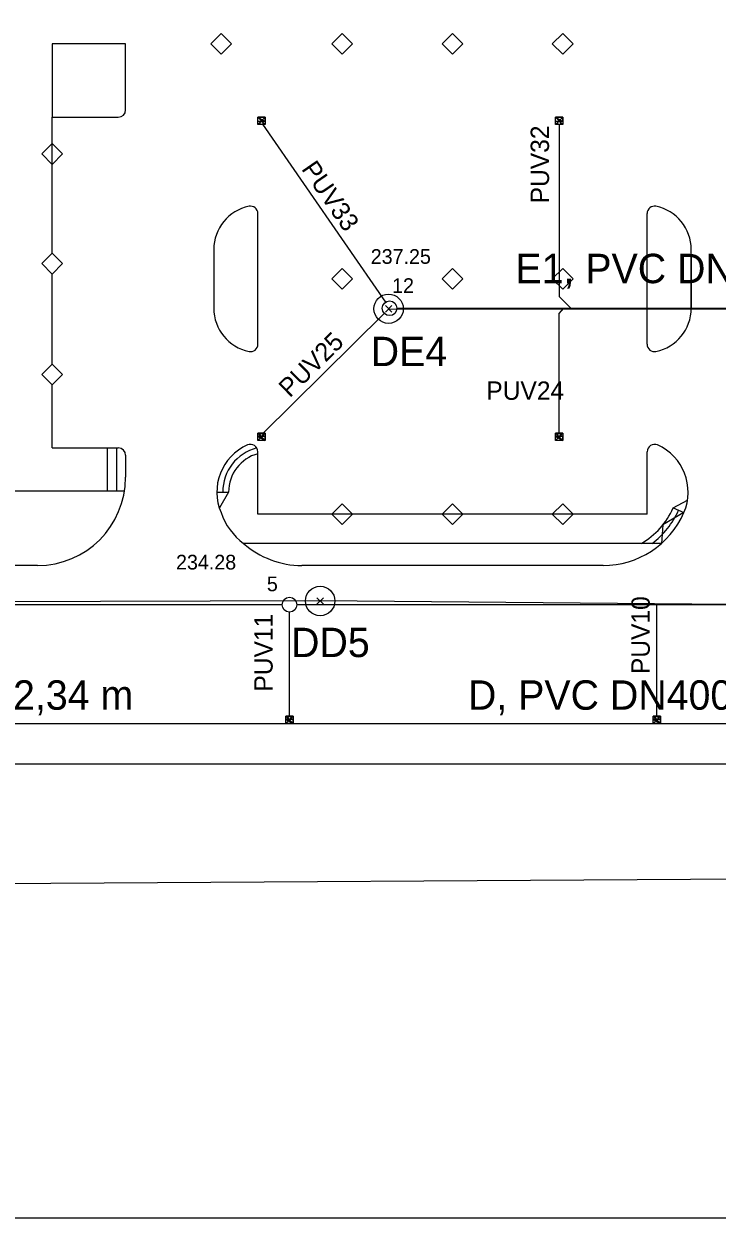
# Model space of a CAD drawing. Extents: x -264234 to -263604, y -1242346 to -1242049.
# Drawn here: x -263972 to -263924.8, y -1242345.9 to -1242264.6 of the extents above; entities that cross this region are included whole.
import ezdxf

# ---------------------------------------------------------------- set-up
doc = ezdxf.new("R2010")
doc.units = 0
for name, color, linetype in [('KFA_BODY_CISLO', 7, 'Continuous'), ('KFA_BODY_SYMBOL', 7, 'Continuous'), ('KFA_BODY_VYSKA', 7, 'Continuous'), ('KFA_DAZDOVA_KANALIZACIA_vetva_D', 7, 'Continuous'), ('KFA_DAZDOVA_KANALIZACIA_vetva_D_popis', 7, 'Continuous'), ('KFA_DAZDOVA_KANALIZACIA_vetva_E', 7, 'Continuous'), ('KFA_DAZDOVA_KANALIZACIA_vetva_E_popis', 7, 'Continuous'), ('KFA_SITUACIA_DSP', 7, 'Continuous'), ('KFA_SO_40-2-II_DK_PRIPOJKY_UV_PROJEKT', 7, 'Continuous'), ('KFA_SO_40-2-II_DK_PRIPOJKY_UV_PROJEKT_popis', 7, 'Continuous'), ('KFA_SO_40-2-II_DK_UV_PROJEKT', 7, 'Continuous'), ('RAM_NA_TLAC_1-500', 7, 'Continuous')]:
    doc.layers.add(name, color=color, linetype=linetype)

msp = doc.modelspace()

# ---------------------------------------------------------------- linework, layer by layer
at = {"layer": 'KFA_BODY_SYMBOL'}
for p, q in [((-263947.392, -1242284.234), (-263946.95, -1242283.792)), ((-263946.95, -1242284.234), (-263947.392, -1242283.792)), ((-263952.051, -1242304.117), (-263951.609, -1242303.675)), ((-263951.609, -1242304.117), (-263952.051, -1242303.675))]:
    msp.add_line(p, q, dxfattribs=at)
at = {"layer": 'KFA_DAZDOVA_KANALIZACIA_vetva_D'}
msp.add_lwpolyline([(-263821.591, -1242304.454), (-263853.822, -1242304.119), (-263903.787, -1242304.318), (-263951.83, -1242303.896), (-264004.174, -1242304.048), (-264044.816, -1242304.218), (-264095.209, -1242304.148), (-264105.621, -1242304.173)], dxfattribs=at)
msp.add_circle((-263951.83, -1242303.896), 1, dxfattribs=at)
at = {"layer": 'KFA_DAZDOVA_KANALIZACIA_vetva_E'}
msp.add_line((-263947.171, -1242284.013), (-263904.009, -1242284.08), dxfattribs=at)
msp.add_circle((-263947.171, -1242284.013), 1, dxfattribs=at)
at = {"layer": 'KFA_SITUACIA_DSP'}
for p, q in [((-263965.068, -1242265.982), (-263970.068, -1242265.982)), ((-263965.068, -1242270.482), (-263965.068, -1242265.982)), ((-263970.065, -1242280.238), (-263970.068, -1242270.982)), ((-263956.068, -1242270.982), (-263955.568, -1242270.982)), ((-263956.068, -1242271.272), (-263956.068, -1242270.982)), ((-263956.068, -1242270.982), (-263955.568, -1242271.272)), ((-263956.068, -1242270.982), (-263955.568, -1242271.272)), ((-263955.568, -1242270.982), (-263956.068, -1242270.982)), ((-263955.568, -1242271.272), (-263956.068, -1242271.272)), ((-263955.761, -1242271.455), (-263947.392, -1242283.571)), ((-263955.568, -1242270.982), (-263955.568, -1242271.272)), ((-263955.568, -1242271.272), (-263955.568, -1242270.982)), ((-263935.824, -1242270.983), (-263935.324, -1242270.983)), ((-263935.824, -1242271.273), (-263935.824, -1242270.983)), ((-263935.824, -1242270.983), (-263935.324, -1242271.273)), ((-263935.824, -1242270.983), (-263935.324, -1242271.273)), ((-263935.324, -1242270.983), (-263935.824, -1242270.983)), ((-263935.324, -1242271.273), (-263935.824, -1242271.273)), ((-263935.574, -1242271.473), (-263935.574, -1242283.187)), ((-263935.324, -1242270.983), (-263935.324, -1242271.273)), ((-263935.324, -1242271.273), (-263935.324, -1242270.983)), ((-263956.068, -1242286.432), (-263956.068, -1242277.533)), ((-263929.58, -1242286.432), (-263929.58, -1242277.533)), ((-263959.068, -1242279.982), (-263959.068, -1242283.982)), ((-263926.58, -1242283.982), (-263926.58, -1242279.982)), ((-263926.58, -1242280.482), (-263926.58, -1242283.982)), ((-263970.068, -1242287.775), (-263970.068, -1242281.649)), ((-263935.574, -1242283.187), (-263934.779, -1242283.982)), ((-263955.747, -1242292.522), (-263947.464, -1242284.334)), ((-263946.608, -1242283.982), (-263908.955, -1242283.982)), ((-263946.608, -1242283.982), (-263904.413, -1242283.982)), ((-263935.574, -1242284.343), (-263935.249, -1242283.982)), ((-263935.574, -1242292.492), (-263935.574, -1242284.343)), ((-263970.068, -1242293.482), (-263970.068, -1242289.189)), ((-263956.068, -1242292.692), (-263955.568, -1242292.692)), ((-263956.068, -1242292.982), (-263956.068, -1242292.692)), ((-263956.068, -1242292.692), (-263955.568, -1242292.982)), ((-263956.068, -1242292.692), (-263955.568, -1242292.982)), ((-263955.568, -1242292.692), (-263956.068, -1242292.692)), ((-263955.568, -1242292.982), (-263956.068, -1242292.982)), ((-263955.568, -1242292.692), (-263955.568, -1242292.982)), ((-263955.568, -1242292.982), (-263955.568, -1242292.692)), ((-263935.824, -1242292.692), (-263935.324, -1242292.692)), ((-263935.824, -1242292.982), (-263935.824, -1242292.692)), ((-263935.824, -1242292.692), (-263935.324, -1242292.982)), ((-263935.824, -1242292.692), (-263935.324, -1242292.982)), ((-263935.324, -1242292.692), (-263935.824, -1242292.692)), ((-263935.324, -1242292.982), (-263935.824, -1242292.982)), ((-263935.324, -1242292.692), (-263935.324, -1242292.982)), ((-263935.324, -1242292.982), (-263935.324, -1242292.692)), ((-263970.068, -1242293.482), (-263965.568, -1242293.482)), ((-263966.314, -1242293.482), (-263966.314, -1242296.432)), ((-263965.684, -1242293.482), (-263965.684, -1242296.432)), ((-263965.068, -1242293.982), (-263965.068, -1242295.482)), ((-263956.068, -1242297.982), (-263956.068, -1242293.737)), ((-263929.58, -1242297.982), (-263929.58, -1242293.737)), ((-263927.814, -1242297.562), (-263926.833, -1242297.035)), ((-263929.58, -1242297.982), (-263956.068, -1242297.982)), ((-263927.814, -1242297.562), (-263927.081, -1242297.882)), ((-263928.612, -1242299.982), (-263957.036, -1242299.982)), ((-263971.068, -1242301.482), (-264112.961, -1242301.482)), ((-263932.58, -1242301.482), (-263953.068, -1242301.482)), ((-263954.413, -1242304.147), (-264003.396, -1242304.147)), ((-263953.913, -1242311.742), (-263953.913, -1242304.647)), ((-263904.413, -1242304.147), (-263953.413, -1242304.147)), ((-263928.913, -1242311.742), (-263928.913, -1242304.147)), ((-263954.163, -1242311.942), (-263953.663, -1242311.942)), ((-263954.163, -1242312.232), (-263954.163, -1242311.942)), ((-263954.163, -1242311.942), (-263953.663, -1242312.232)), ((-263954.163, -1242311.942), (-263953.663, -1242312.232)), ((-263953.663, -1242311.942), (-263954.163, -1242311.942)), ((-263953.663, -1242311.942), (-263953.663, -1242312.232)), ((-263953.663, -1242312.232), (-263953.663, -1242311.942)), ((-263929.163, -1242311.942), (-263928.663, -1242311.942)), ((-263929.163, -1242312.232), (-263929.163, -1242311.942)), ((-263929.163, -1242311.942), (-263928.663, -1242312.232)), ((-263929.163, -1242311.942), (-263928.663, -1242312.232)), ((-263928.663, -1242311.942), (-263929.163, -1242311.942)), ((-263928.663, -1242311.942), (-263928.663, -1242312.232)), ((-263928.663, -1242312.232), (-263928.663, -1242311.942)), ((-263980.94, -1242312.232), (-263857.327, -1242312.232)), ((-263953.663, -1242312.232), (-263954.163, -1242312.232)), ((-263928.663, -1242312.232), (-263929.163, -1242312.232)), ((-264038.443, -1242314.982), (-263836.403, -1242314.982)), ((-263976.89, -1242323.14), (-263880.39, -1242322.51))]:
    msp.add_line(p, q, dxfattribs=at)
for points in [[(-263958.568, -1242265.275), (-263957.861, -1242265.982), (-263958.568, -1242266.689), (-263959.275, -1242265.982)], [(-263950.324, -1242265.275), (-263949.617, -1242265.982), (-263950.324, -1242266.689), (-263951.031, -1242265.982)], [(-263942.824, -1242265.275), (-263942.117, -1242265.982), (-263942.824, -1242266.689), (-263943.531, -1242265.982)], [(-263935.324, -1242265.275), (-263934.617, -1242265.982), (-263935.324, -1242266.689), (-263936.031, -1242265.982)], [(-263970.068, -1242272.775), (-263969.361, -1242273.482), (-263970.068, -1242274.189), (-263970.775, -1242273.482)], [(-263970.068, -1242280.235), (-263969.361, -1242280.942), (-263970.068, -1242281.649), (-263970.775, -1242280.942)], [(-263950.324, -1242281.275), (-263949.617, -1242281.982), (-263950.324, -1242282.689), (-263951.031, -1242281.982)], [(-263942.824, -1242281.275), (-263942.117, -1242281.982), (-263942.824, -1242282.689), (-263943.531, -1242281.982)], [(-263935.324, -1242281.275), (-263934.617, -1242281.982), (-263935.324, -1242282.689), (-263936.031, -1242281.982)], [(-263970.068, -1242287.775), (-263969.361, -1242288.482), (-263970.068, -1242289.189), (-263970.775, -1242288.482)], [(-263949.617, -1242297.982), (-263950.324, -1242297.275), (-263951.031, -1242297.982), (-263950.324, -1242298.689)], [(-263942.117, -1242297.982), (-263942.824, -1242297.275), (-263943.531, -1242297.982), (-263942.824, -1242298.689)], [(-263934.617, -1242297.982), (-263935.324, -1242297.275), (-263936.031, -1242297.982), (-263935.324, -1242298.689)]]:
    msp.add_lwpolyline(points, close=True, dxfattribs=at)
for points in [[(-263970.068, -1242265.982), (-263970.068, -1242270.982), (-263965.568, -1242270.982)], [(-263965.143, -1242296.432), (-264120.018, -1242296.432), (-264120.282, -1242296.432)], [(-263958.859, -1242296.482), (-263958.059, -1242296.482), (-263958.688, -1242297.562)], [(-263927.081, -1242297.882), (-263928.506, -1242298.713), (-263928.612, -1242299.982)]]:
    msp.add_lwpolyline(points, dxfattribs=at)
for centre, radius in [((-263955.818, -1242271.373), 0.1), ((-263935.574, -1242271.373), 0.1), ((-263947.108, -1242283.982), 0.5), ((-263955.818, -1242292.592), 0.1), ((-263935.574, -1242292.592), 0.1), ((-263953.913, -1242304.147), 0.5), ((-263953.913, -1242311.842), 0.1), ((-263928.913, -1242311.842), 0.1)]:
    msp.add_circle(centre, radius, dxfattribs=at)
for centre, radius, start, end in [((-263965.568, -1242270.482), 0.5, 270, 0), ((-263956.068, -1242279.982), 3, 101.53696, 180), ((-263956.568, -1242277.533), 0.5, 0, 101.53696), ((-263929.08, -1242277.533), 0.5, 78.46304, 180), ((-263929.58, -1242279.982), 3, 0, 78.46304), ((-263956.068, -1242283.982), 3, 180, 258.46304), ((-263929.58, -1242283.982), 3, 281.53696, 0), ((-263956.568, -1242286.432), 0.5, 258.46304, 0), ((-263929.08, -1242286.432), 0.5, 180, 281.53696), ((-263955.359, -1242296.482), 3.5, 113.75985, 203.57818), ((-263956.568, -1242293.737), 0.5, 0, 113.75985), ((-263929.08, -1242293.737), 0.5, 66.24015, 180), ((-263930.289, -1242296.482), 3.5, 336.42182, 66.24015), ((-263965.568, -1242293.982), 0.5, 0, 90), ((-263955.359, -1242296.482), 3.1, 104.54571, 180), ((-263955.359, -1242296.482), 2.7, 105.21758, 180), ((-263971.068, -1242295.482), 6, 270, 0), ((-263954.444, -1242296.485), 4.353, 198.7173, 233.45125), ((-263932.58, -1242295.482), 6, 270, 336.42182), ((-263932.58, -1242295.482), 5.2, 300.07335, 336.42182), ((-263932.58, -1242295.482), 5.6, 306.52749, 336.42182), ((-263953.068, -1242295.482), 6, 228.59038, 270)]:
    msp.add_arc(centre, radius, start, end, dxfattribs=at)
at = {"layer": 'KFA_SO_40-2-II_DK_PRIPOJKY_UV_PROJEKT'}
for points in [[(-263955.761, -1242271.455), (-263947.392, -1242283.571)], [(-263935.574, -1242271.473), (-263935.574, -1242283.187), (-263934.779, -1242283.982)], [(-263955.747, -1242292.522), (-263947.464, -1242284.334)], [(-263935.574, -1242292.492), (-263935.574, -1242284.343), (-263935.249, -1242283.982)], [(-263953.913, -1242311.742), (-263953.913, -1242304.647)], [(-263928.913, -1242311.742), (-263928.913, -1242304.147)]]:
    msp.add_lwpolyline(points, dxfattribs=at)
at = {"layer": 'KFA_SO_40-2-II_DK_UV_PROJEKT'}
for points in [[(-263956.068, -1242271.482), (-263956.068, -1242270.982), (-263955.568, -1242270.982), (-263955.568, -1242271.482), (-263956.068, -1242271.482), (-263955.568, -1242270.982), (-263956.068, -1242270.982), (-263955.568, -1242271.482)], [(-263935.824, -1242271.483), (-263935.824, -1242270.983), (-263935.324, -1242270.983), (-263935.324, -1242271.483), (-263935.824, -1242271.483), (-263935.324, -1242270.983), (-263935.824, -1242270.983), (-263935.324, -1242271.483)], [(-263956.068, -1242292.982), (-263956.068, -1242292.482), (-263955.568, -1242292.482), (-263955.568, -1242292.982), (-263956.068, -1242292.982), (-263955.568, -1242292.482), (-263956.068, -1242292.482), (-263955.568, -1242292.982)], [(-263935.824, -1242292.982), (-263935.824, -1242292.482), (-263935.324, -1242292.482), (-263935.324, -1242292.982), (-263935.824, -1242292.982), (-263935.324, -1242292.482), (-263935.824, -1242292.482), (-263935.324, -1242292.982)], [(-263954.163, -1242312.232), (-263954.163, -1242311.732), (-263953.663, -1242311.732), (-263953.663, -1242312.232), (-263954.163, -1242312.232), (-263953.663, -1242311.732), (-263954.163, -1242311.732), (-263953.663, -1242312.232)], [(-263929.163, -1242312.232), (-263929.163, -1242311.732), (-263928.663, -1242311.732), (-263928.663, -1242312.232), (-263929.163, -1242312.232), (-263928.663, -1242311.732), (-263929.163, -1242311.732), (-263928.663, -1242312.232)]]:
    msp.add_lwpolyline(points, dxfattribs=at)
at = {"layer": 'RAM_NA_TLAC_1-500'}
msp.add_lwpolyline([(-264234.177, -1242048.883), (-263604.177, -1242048.883), (-263604.177, -1242345.883), (-264234.177, -1242345.883)], close=True, dxfattribs=at)

# ---------------------------------------------------------------- texts
at = {"layer": 'KFA_BODY_CISLO'}
for s, p in [('12', (-263946.933, -1242282.937)), ('5', (-263955.454, -1242303.234))]:
    msp.add_text(s, height=1, dxfattribs=at).set_placement(p)
at = {"layer": 'KFA_BODY_VYSKA'}
for s, p in [('237.25', (-263948.386, -1242280.957)), ('234.28', (-263961.635, -1242301.753))]:
    msp.add_text(s, height=1, dxfattribs=at).set_placement(p)
at = {"layer": 'KFA_DAZDOVA_KANALIZACIA_vetva_D_popis'}
for s, p in [('DD5', (-263953.806, -1242307.713)), ('D, PVC DN400 - 52,34 m', (-263994.572, -1242311.294)), ('D, PVC DN400 - 48,05 m', (-263941.772, -1242311.294))]:
    msp.add_text(s, height=2, dxfattribs=at).set_placement(p)
at = {"layer": 'KFA_DAZDOVA_KANALIZACIA_vetva_E_popis'}
for s, p in [('E1, PVC DN300 - 43,16 m', (-263938.542, -1242282.273)), ('DE4', (-263948.389, -1242287.917))]:
    msp.add_text(s, height=2, dxfattribs=at).set_placement(p)
at = {"layer": 'KFA_SO_40-2-II_DK_PRIPOJKY_UV_PROJEKT_popis'}
for s, rotation, p in [('PUV32', 90, (-263936.255, -1242276.843)), ('PUV33', 304.63248, (-263953.143, -1242274.503)), ('PUV25', 44.66918, (-263953.899, -1242290.105)), ('PUV10', 90, (-263929.399, -1242308.87)), ('PUV11', 90, (-263955.062, -1242310.059))]:
    msp.add_text(s, height=1.25, rotation=rotation, dxfattribs=at).set_placement(p)
msp.add_text('PUV24', height=1.25, dxfattribs=at).set_placement((-263940.522, -1242290.209))

doc.saveas('drawing.dxf')
